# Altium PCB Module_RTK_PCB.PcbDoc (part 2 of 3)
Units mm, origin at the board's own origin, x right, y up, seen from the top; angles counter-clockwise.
Board outline 99.98 x 60 mm, 4 copper layers (Top Layer, gnd, vcc, Bottom Layer), stack 1.536 mm thick; 168 components, 121 nets, 582 pads, 666 vias.
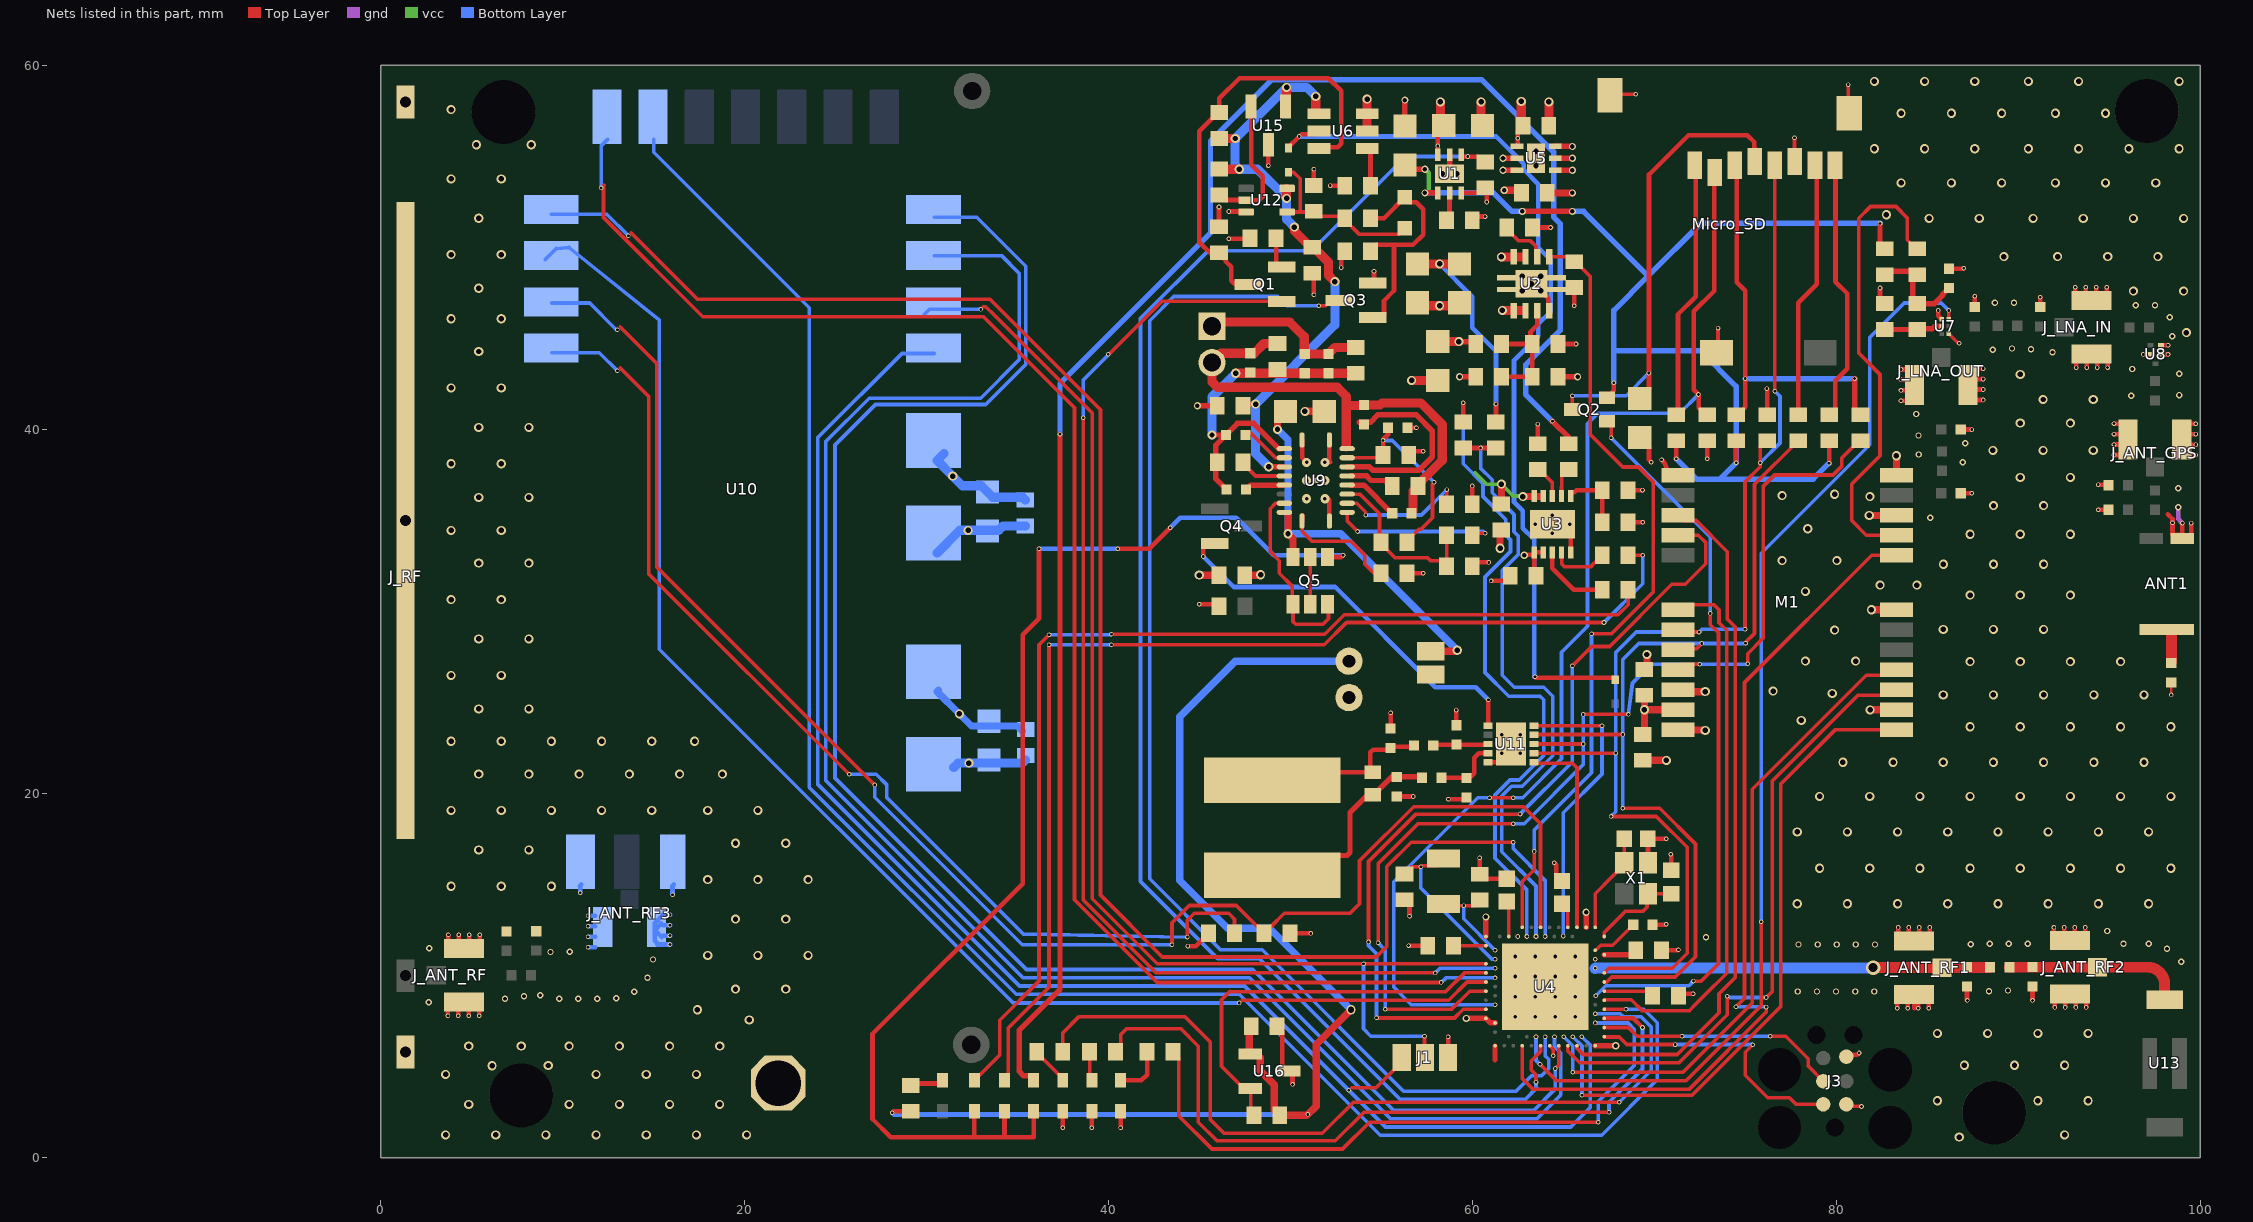
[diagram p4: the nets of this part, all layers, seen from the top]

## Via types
v1: diameter 0.5, hole 0.3, Top Layer to Bottom Layer, 281 vias
v2: diameter 0.25, hole 0.15, Top Layer to Bottom Layer, 274 vias
v3: diameter 0.35, hole 0.2, Top Layer to Bottom Layer, 58 vias
v4: diameter 0.5, hole 0.2, Top Layer to Bottom Layer, 30 vias
v5: diameter 0.4, hole 0.25, Top Layer to Bottom Layer, 20 vias
v6: diameter 0.8, hole 0.5, Top Layer to Bottom Layer, 2 vias
v7: diameter 0.5, hole 0.35, Top Layer to Bottom Layer, 1 vias

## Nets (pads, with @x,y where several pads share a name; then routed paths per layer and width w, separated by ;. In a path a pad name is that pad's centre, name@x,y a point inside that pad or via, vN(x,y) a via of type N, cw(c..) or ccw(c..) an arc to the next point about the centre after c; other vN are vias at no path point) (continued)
GND: ANT1.1 C1.1 C2.1 C3.1 C4.1 C5.1 C6.1 C7.1 C8.1 C9.1 C10.1 C11.1 C12.1 C13.1 C14.1 C15.1 C16.1 C17.2 C18.1 C19.2 C20.2 C22.1 C23.1 C24.1 C25.1 C26.1 C27.2 C28.1 C29.1 C30.1 C31.1 C32.1 C33.1 C35.1 C36.1 C37.1 C38.1 C39.1 C40.1 C41.1 C42.2 C43.1 C44.2 C45.1 C46.1 C47.1 C48.1 C49.2 C51.2 C53.2 C54.1 C55.1 C56.2 C60.1 C62.1 J1.1 J3.5 J_ANT_GPS.2 J_ANT_RF1.2 J_ANT_RF2.2 J_ANT_RF3.2 J_ANT_RF.2 J_BAT.1 J_charge_5v.1 J_LNA_IN.2 J_LNA_OUT.2 J_RF.2 J_RF.3 LED4.2 LED5.2 LED6.2 M1.2 M1.7 M1.10 M1.12 M1.13 M1.24 Micro_SD.0 Micro_SD.6 PAD_GND.0 Q3.2 R3.1 R7.1 R8.1 R9.1 R16.1 R20.1 R24.1 R25.2 R30.1 R33.2 R36.1 R38.1 R42.1 R48.2 R49.2 R51.1 U1.0 U1.3 U1.5 U2.0 U2.4 U3.0 U3.5 U4.74 U4.AD2 U4.B7 U4.F23 U5.0 U5.2 U5.3 U5.5 U7.1 U7.4 U8.2 U8.3 U8.5 U9.1 U9.11 U9.20 U9.21 U10.2 U10.3 U10.20 U10.22 U11.5 U11.11 U12.3 U15.3 U16.3 X1.2 | length 174
  Top Layer w0.15: v2(98.375,25.423) C40.1@98.375,26.108
  Top Layer w0.2: U11.11@62.1,22.64 U11.11@62.642,23.183 ; Micro_SD.0@67.54,58.375 67.59,58.425 v2(68.95,58.425) ; Micro_SD.0@73.39,44.225 73.475,44.31 v2(73.475,45.575) ; v2(77.675,56.025) 77.675,54.75 Micro_SD.6@77.7,54.725 ; v2(80.625,58.95) 80.625,57.44 Micro_SD.0@80.69,57.375 ; U7.4@86.154,45.267 86.678,44.743 86.715,44.743 v2(86.725,44.733)
  Top Layer w0.254: v2(3.7,7.8) J_ANT_RF.2@3.7,8.19 ; J_ANT_RF.2@3.728,11.86 v2(3.728,12.25) ; v2(4.275,7.8) J_ANT_RF.2@4.275,8.19 ; J_ANT_RF.2@4.303,11.86 v2(4.303,12.25) ; v2(4.85,7.8) J_ANT_RF.2@4.85,8.19 ; J_ANT_RF.2@4.877,11.86 v2(4.877,12.25) ; v2(5.425,7.8) J_ANT_RF.2@5.425,8.19 ; J_ANT_RF.2@5.453,11.86 v2(5.453,12.25) ; v2(37.475,1.65) LED6.2@37.475,2.55 ; v2(39.075,1.65) LED5.2@39.075,2.55 ; v2(40.654,1.65) LED4.2@40.654,2.55 ; v2(44.975,30.4) 45.964,30.4 R36.1@46.064,30.3 ; v2(46.059,52.226) 46.059,51.139 C45.1@46.061,51.137 ; v2(46.602,50.477) 47.541,50.477 47.664,50.6 R49.2@47.764,50.5 ; v2(46.602,51.978) 47.478,51.978 47.5,52 U12.3@47.55,51.95 ; v2(48.775,54.5) U15.3@48.775,55.65 ; C47.1@49.251,7.209 49.53,6.929 49.53,4.923 49.703,4.75 U16.3@49.875,4.75 50,4.75 50.1,4.65 v2(50.1,4.025) ; R30.1@49.962,12.319 v2(51.101,12.319) ; U9.1@50.625,39.425 50.625,38.45 v4@50.775,38.3 ; C37.1@51.175,48.589 51.275,48.589 v2(51.275,47.4) ; R25.2@51.275,53.411 v2(51.275,54.3) ; C55.1@51.742,41.1 C55.1@51.842,41 ; v4@52.075,36.2 52.125,36.15 U9.11@52.125,34.975 ; U9.20@52.125,39.425 52.125,38.25 52.175,38.2 ; v2(52.175,53.4) R24.1@52.964,53.4 ; v2(52.775,48.9) 52.775,49.611 C48.1@52.964,49.8 ; Q3.2@54.5,48.05 54.575,48.125 v2(54.575,48.7) ; C32.1@55.487,23.571 v2(55.487,24.437) ; C35.1@55.812,19.828 55.825,19.828 55.838,19.842 v2(56.726,19.842) ; C20.2@56.25,14.164 56.528,13.886 v2(56.528,13.264) ; R38.1@56.386,32.1 v2(57.275,32.1) ; v2(56.475,11.65) C26.1@57.528,11.65 ; C60.1@56.486,38.6 56.686,38.8 v2(57.286,38.8) ; C62.1@56.508,40.1 v2(56.908,40.1) ; U1.0@58.275,54.1 58.283,54.1 U1.0@58.725,54.542 ; J1.1@58.645,5.5 v2(58.645,6.65) ; v2(58.663,19.692) 59.55,19.692 C36.1@59.65,19.792 ; C33.1@59.1,23.758 v2(59.1,24.592) ; C56.2@59.209,46.9 C56.2@59.275,46.966 ; U1.3@59.375,53 60.475,53 R20.1@60.675,53.2 ; R42.1@59.975,32.5 60.175,32.7 v2(60.875,32.7) ; R33.2@59.975,35.9 v2(59.975,36.9) ; C3.1@59.975,51.5 60.175,51.7 v2(60.675,51.7) ; v2(60.375,16.475) C19.2@60.375,15.572 60.622,15.325 C29.1@61.875,15.325 ; R20.1@60.675,53.278 60.775,53.178 v2(60.775,52.5) ; U11.5@60.83,21.725 61.412,21.725 62.1,22.413 62.1,22.64 U11.11@62.1,22.725 ; v2(61.008,31.686) 61.772,31.686 C5.1@62.058,31.971 ; 61.225,5.35 U4.AD2@61.225,6.15 ; C54.1@62.475,53.2 62.525,53.15 C54.1@62.675,53 ; R7.1@63.575,39.222 v2(63.575,40.3) ; U2.0@63.825,47.612 63.825,47.537 64.152,47.21 64.152,46.585 U2.4@64.2,46.537 ; C53.2@64.275,56.6 C53.2@64.454,56.421 ; U5.3@64.454,55.573 64.477,55.55 U5.3@64.525,55.55 U5.3@64.548,55.573 ; v2(64.475,16.2) 64.577,16.098 64.577,15.523 C28.1@64.9,15.2 ; U5.2@64.525,54.9 U5.2@64.549,54.924 ; R3.1@64.686,44.7 v2(65.675,44.7) ; U3.5@65.375,33.25 U3.0@65.375,34.7 ; v2(65.575,46.8) R16.1@65.575,47.789 ; R9.1@68.536,34.9 v2(69.336,34.9) ; R8.1@68.536,36.675 v2(69.325,36.675) ; C43.1@69.175,39.566 69.683,39.058 69.683,38.333 v2(69.81,38.206) ; C15.1@69.35,26.853 69.403,26.8 C15.1@69.425,26.822 C15.1@69.567,26.964 ; X1.2@69.725,16.35 69.625,16.45 C18.1@69.625,17.525 v2(70.625,17.525) ; C27.2@69.883,12.8 70.6,12.8 v2(70.625,12.825) ; C31.1@70.375,11.4 71.275,11.4 v2(71.3,11.425) ; v2(70.375,38.333) 70.557,38.152 70.678,37.773 70.951,37.5 M1.13@71.275,37.5 ; v2(70.875,16.675) 70.9,16.65 C17.2@70.9,15.8 ; C30.1@71.3,8.9 71.325,8.875 71.45,9 v2(72.103,9) ; v2(72.875,38.4) R48.2@72.875,39.389 ; v2(76.15,42.25) 76.175,42.225 R51.1@76.175,40.811 ; J3.5@80.525,5.55 80.628,5.653 81.127,5.653 v2(81.224,5.749) ; C44.2@82.375,47.111 v2(82.375,47.775) ; M1.10@83.275,35.3 M1.10@83.35,35.225 ; v2(83.319,8.202) J_ANT_RF1.2@83.319,8.592 ; J_ANT_RF1.2@83.375,12.26 v2(83.375,12.65) ; v2(83.525,41.575) J_LNA_OUT.2@83.915,41.575 ; v2(83.525,42.15) J_LNA_OUT.2@83.915,42.15 ; v2(83.525,42.725) J_LNA_OUT.2@83.915,42.725 ; v2(83.525,43.3) J_LNA_OUT.2@83.915,43.3 ; v2(83.894,8.202) J_ANT_RF1.2@83.894,8.592 ; J_ANT_RF1.2@83.95,12.26 v2(83.95,12.65) ; 84.249,8.202 J_ANT_RF1.2@84.249,8.592 ; v2(84.469,8.202) J_ANT_RF1.2@84.469,8.592 ; J_ANT_RF1.2@84.525,12.26 v2(84.525,12.65) ; v2(85.043,8.202) J_ANT_RF1.2@85.043,8.592 ; J_ANT_RF1.2@85.1,12.26 v2(85.1,12.65) ; v2(85.567,46.542) 85.567,46.254 U7.1@85.754,46.067 ; C42.2@86.154,48.833 86.954,48.833 v2(86.979,48.858) ; C22.1@86.808,36.5 v2(87.412,36.5) ; C23.1@86.808,40 v2(87.412,40) ; C41.1@87.15,9.405 87.15,8.663 v2(87.175,8.638) ; C24.1@87.575,46.733 v2(87.575,47.324) ; J_LNA_OUT.2@87.66,41.625 v2(88.05,41.625) ; J_LNA_OUT.2@87.66,42.2 v2(88.05,42.2) ; J_LNA_OUT.2@87.66,42.775 v2(88.05,42.775) ; J_LNA_OUT.2@87.66,43.35 v2(88.05,43.35) ; v2(90.75,8.638) C46.1@90.75,9.405 ; C25.1@91.175,46.733 v2(91.175,47.269) ; J_ANT_RF2.2@91.926,12.258 v2(91.926,12.648) ; v2(91.974,8.252) J_ANT_RF2.2@91.974,8.642 ; J_ANT_RF2.2@92.501,12.258 v2(92.501,12.648) ; v2(92.55,8.252) J_ANT_RF2.2@92.55,8.642 ; J_ANT_RF2.2@93.075,12.258 v2(93.075,12.648) ; J_LNA_IN.2@93.101,47.433 v2(93.101,47.823) ; v2(93.124,8.252) J_ANT_RF2.2@93.124,8.642 ; v2(93.149,43.402) J_LNA_IN.2@93.149,43.792 ; J_ANT_RF2.2@93.651,12.258 v2(93.651,12.648) ; J_LNA_IN.2@93.676,47.433 v2(93.676,47.823) ; v2(93.699,8.252) J_ANT_RF2.2@93.699,8.642 ; v2(93.725,43.402) J_LNA_IN.2@93.725,43.792 ; J_LNA_IN.2@94.25,47.433 v2(94.25,47.823) ; v2(94.299,43.402) J_LNA_IN.2@94.299,43.792 ; v2(94.364,35.592) C39.1@94.896,35.592 ; v2(94.364,36.975) 94.896,36.975 C38.1@94.933,36.938 ; J_LNA_IN.2@94.826,47.433 v2(94.826,47.823) ; v2(94.874,43.402) J_LNA_IN.2@94.874,43.792 ; v2(95.227,38.601) J_ANT_GPS.2@95.617,38.601 ; v2(95.227,39.176) J_ANT_GPS.2@95.617,39.176 ; v2(95.227,39.75) J_ANT_GPS.2@95.617,39.75 ; v2(95.227,40.326) J_ANT_GPS.2@95.617,40.326 ; v2(96.827,44.125) U8.5@97.227,44.125 ; U8.2@97.802,44.125 v2(98.196,44.125) ; U8.3@97.802,44.625 v2(98.196,44.625) ; 98.171,35.353 98.44,35.084 v2(98.44,34.875) 98.44,34.217 98.448,34.225 ANT1.1@98.985,34.225 ; v2(98.985,34.861) ANT1.1@98.985,34.225 ; ANT1.1@99.012,34.037 98.985,34.064 ANT1.1@98.985,34.225 ; J_ANT_GPS.2@99.333,38.599 v2(99.723,38.599) ; J_ANT_GPS.2@99.333,39.175 v2(99.723,39.175) ; J_ANT_GPS.2@99.333,39.749 v2(99.723,39.749) ; J_ANT_GPS.2@99.333,40.324 v2(99.723,40.324) ; v2(99.466,34.861) 99.466,34.286 ANT1.1@99.475,34.277
  Top Layer w0.3: v5(44.875,41.3) C51.2@45.964,41.3 ; C2.1@56.275,56.667 v5(56.275,58.1) ; U1.0@58.725,54.542 U1.5@58.725,55.1 ; v5(61.662,54.9) U5.5@62.425,54.9 ; C7.1@63.286,51.1 v2(64.275,51.1) ; U5.3@64.571,55.55 v5(65.475,55.55) ; U5.2@64.573,54.9 v5(65.475,54.9)
  Top Layer w0.4: v1(44.975,32) C49.2@46.053,32 ; v1(50.775,41) 51.51,41 51.576,40.934 C55.1@51.742,41.1 ; v1(61.5,33.478) C8.1@61.5,34.449 ; v5(61.725,53.15) 62.525,53.15 C54.1@62.594,53.15 ; C16.1@69.235,21.826 v1(70.635,21.826) ; C15.1@69.567,26.964 v1(69.567,27.642) ; M1.24@71.575,23.5 72.75,23.5 v1(72.775,23.475) ; v1(81.783,35.282) 83.268,35.282 M1.10@83.3,35.25 ; v1(81.825,24.6) M1.2@83.225,24.6 ; v1(81.9,30.1) M1.7@83.275,30.1 M1.7@83.3,30.1 ; M1.12@83.275,37.5 v1(83.275,38.561)
  Top Layer w0.5: v1(56.64,42.7) C6.1@58.075,42.7 ; C4.1@57.375,46.8 v1(58.175,46.8) C56.2@59.275,46.8 ; C1.1@60.458,57.211 v1(60.458,58) ; C53.2@64.183,57.011 v1(64.183,58)
  gnd w0.254: v3(98.749,35.723) 98.749,35.098 v2(98.985,34.861)
  gnd w0.5: 64.398,7.261 64.525,7.388 v4(64.525,7.75) ; v4(62.325,8.85) v4(62.325,9.95) ; v4(62.325,8.85) v4(62.325,7.75) v4(63.425,7.75) ; v4(62.325,8.85) v4(63.425,8.85) ; v4(62.325,9.95) v4(62.325,11.05) v4(63.425,11.05) ; v4(62.325,9.95) v4(63.425,9.95) ; v4(63.425,7.75) v4(63.425,8.85) ; v4(63.425,7.75) v4(64.525,7.75) ; v4(63.425,8.85) v4(63.425,9.95) ; v4(63.425,8.85) v4(64.525,8.85) ; v4(63.425,9.95) v4(63.425,11.05) ; v4(63.425,9.95) v4(64.525,9.95) ; v4(63.425,11.05) v4(64.525,11.05) ; v4(64.525,7.75) v4(64.525,8.85) ; v4(64.525,7.75) v4(65.625,7.75) v4(65.625,8.85) ; v4(64.525,8.85) v4(64.525,9.95) ; v4(64.525,8.85) v4(65.625,8.85) ; v4(64.525,9.95) v4(64.525,11.05) ; v4(64.525,9.95) v4(65.625,9.95) ; v4(64.525,11.05) v4(65.625,11.05) v4(65.625,9.95) ; v4(65.625,8.85) v4(65.625,9.95)
  Bottom Layer w0.254: v2(10.966,14.55) 10.966,14.895 10.941,14.92 U10.20@11.026,15.005 ; v2(11.4,11.562) J_ANT_RF3.2@11.79,11.562 ; v2(11.4,12.137) J_ANT_RF3.2@11.79,12.137 ; v2(11.4,12.712) J_ANT_RF3.2@11.79,12.712 ; v2(11.4,13.287) J_ANT_RF3.2@11.79,13.287 ; J_ANT_RF3.2@15.425,12.862 J_ANT_RF3.2@15.063,12.5 ; J_ANT_RF3.2@15.44,12.123 J_ANT_RF3.2@15.063,12.5 ; J_ANT_RF3.2@15.461,13.287 15.063,12.889 J_ANT_RF3.2@15.063,12.5 ; J_ANT_RF3.2@15.508,12.201 v2(15.898,12.201) ; J_ANT_RF3.2@15.508,12.775 v2(15.898,12.775) ; J_ANT_RF3.2@15.508,13.351 v2(15.898,13.351) ; v2(15.898,11.71) 15.898,11.712 15.212,11.712 15.244,11.744 15.063,11.925 J_ANT_RF3.2@15.063,12.5 ; v2(16.041,14.45) 16.041,14.94 U10.22@16.106,15.005
  Bottom Layer w0.4: U10.2@30.65,25.675 30.575,25.6 v1(31.8,24.375) 32.466,23.709 33.425,23.709 34.978,23.709 C12.1@35.267,23.419
  Bottom Layer w0.5: U10.3@30.575,33.22 U10.3@31.825,34.47 ; v1(32.273,34.459) v1@32.284,34.449 ; C10.1@35.425,34.703 34.192,34.703 33.96,34.47 33.35,34.47 v1@32.273,34.47 ; U10.3@31.825,34.47 v1@32.273,34.47 ; U10.3@31.825,34.47 v1@32.273,34.47
  other v1: 86.725,1.125 3.57,1.252 6.327,1.252 9.085,1.252 11.842,1.252 14.599,1.252 17.35,1.252 20.107,1.252 92.518,1.252 4.847,2.925 10.362,2.925 13.119,2.925 15.876,2.925 18.627,2.925 85.529,3.127 91.043,3.127 93.8,3.127 3.57,4.575 11.842,4.575 14.599,4.575 17.35,4.575 6.131,5.05 9.212,5.064 87.004,5.077 89.761,5.077 92.518,5.077 4.847,6.125 7.731,6.125 10.356,6.125 13.119,6.125 15.876,6.125 18.633,6.125 85.529,6.825 88.286,6.825 91.043,6.825 93.8,6.825 20.257,7.565 17.401,8.125 19.5,9.264 22.257,9.264 17.975,11.109 20.732,11.109 23.489,11.109 19.5,13.109 22.257,13.109 77.825,13.95 80.582,13.95 83.339,13.95 86.096,13.95 88.854,13.95 91.611,13.95 94.368,13.95 97.125,13.95 3.871,14.909 6.629,14.909 9.386,14.909 17.975,15.275 20.732,15.275 23.489,15.275 79.05,15.9 81.807,15.9 84.564,15.9 87.321,15.9 90.079,15.9 92.836,15.9 95.593,15.9 98.35,15.9 5.396,16.909 8.154,16.909 19.5,17.275 22.257,17.275 77.825,17.9 80.582,17.9 83.339,17.9 86.096,17.9 88.854,17.9 91.611,17.9 94.368,17.9 97.125,17.9 3.871,19.075 6.629,19.075 9.386,19.075 12.143,19.075 14.9,19.075 17.975,19.075 20.732,19.075 79.05,19.85 81.807,19.85 84.564,19.85 87.321,19.85 90.079,19.85 92.836,19.85 95.593,19.85 98.35,19.85 5.396,21.075 8.154,21.075 10.911,21.075 13.668,21.075 16.425,21.075 18.775,21.075 80.332,21.725 83.089,21.725 85.846,21.725 88.604,21.725 91.361,21.725 94.118,21.725 96.875,21.725 3.871,22.875 6.629,22.875 9.386,22.875 12.143,22.875 14.9,22.875 17.25,22.875 87.321,23.675 90.079,23.675 92.836,23.675 95.593,23.675 98.35,23.675 78.048,24.027 5.396,24.65 8.154,24.65 85.846,25.423 88.604,25.423 91.361,25.423 94.118,25.423 96.875,25.423 79.749,25.502 76.503,25.629 3.871,26.495 6.629,26.495 87.321,27.25 90.079,27.25 92.836,27.25 95.593,27.25 78.274,27.277 81.031,27.277 5.396,28.495 8.154,28.495 79.876,28.977 85.846,29.025 88.604,29.025 91.361,29.025 3.871,30.661 6.629,30.661 87.321,30.9 90.079,30.9 92.836,30.9 78.274,31.106 82.375,31.45 84.4,31.45 85.85,32.6 88.607,32.6 91.364,32.6 5.396,32.661 8.154,32.661 76.992,32.802 80.003,32.802 87.321,34.25 90.079,34.25 92.836,34.25 3.871,34.461 6.629,34.461 78.401,34.55 88.607,35.825 91.364,35.825 5.396,36.275 8.154,36.275 81.814,36.32 76.996,36.373 79.88,36.447 90.079,37.375 92.836,37.375 3.871,38.12 6.629,38.12 88.575,38.85 91.332,38.85 94.089,38.85 5.396,40.12 8.154,40.12 90.079,40.35 92.836,40.35 91.332,41.65 94.089,41.65 3.871,42.286 6.629,42.286 90.079,43.025 5.396,44.286 99.2,45.321 3.871,46.086 6.629,46.086 96.293,47.6 99.05,47.6 5.396,47.76 89.175,49.502 92.129,49.502 94.886,49.502 97.643,49.502 3.871,49.605 6.629,49.605 5.396,51.605 85.068,51.602 87.825,51.602 90.779,51.602 93.536,51.602 96.293,51.602 99.05,51.602 82.725,51.8 83.536,53.552 86.293,53.552 89.05,53.552 92.004,53.552 94.761,53.552 97.518,53.552 3.871,53.771 6.629,53.771 82.061,55.427 84.818,55.427 87.575,55.427 90.529,55.427 93.286,55.427 96.043,55.427 98.8,55.427 5.269,55.644 8.281,55.644 83.536,57.377 86.293,57.377 89.05,57.377 92.004,57.377 94.761,57.377 3.871,57.571 82.061,59.125 84.818,59.125 87.575,59.125 90.529,59.125 93.286,59.125 98.8,59.125
  other v2: 66.725,10.9 62.475,12.15
  other v3: 2.655,8.542 6.839,8.736 9.808,8.736 10.858,8.736 11.908,8.736 12.958,8.758 7.882,8.861 8.775,8.922 13.946,9.114 77.858,9.13 78.908,9.13 79.958,9.13 81.008,9.13 82.058,9.13 88.357,9.149 89.407,9.184 14.664,9.88 98.918,10.768 14.969,10.884 9.338,11.302 10.388,11.314 98.141,11.475 2.678,11.508 77.898,11.708 78.948,11.708 79.998,11.708 81.048,11.708 82.098,11.708 87.348,11.727 88.398,11.747 89.448,11.748 90.498,11.752 95.748,11.752 97.128,11.75 72.816,12.112 94.85,12.45 85.125,35.15 98.764,36.773 86.915,38.211 84.503,38.626 87.064,39.25 84.485,39.676 84.359,40.853 96.172,41.863 98.817,41.894 98.804,43.064 96.225,43.323 91.846,44.25 88.573,44.377 90.67,44.411 89.62,44.449 98.431,45.13 98.294,46.171 96.431,46.832 97.481,46.837 88.686,46.956 89.736,46.972
  other v4: 61.6,22.225 62.6,22.225 61.6,23.225 62.6,23.225 64.375,34.3 63.425,34.8 65.325,34.8 64.375,35.3 50.875,36.2 51.875,36.2 50.875,37.2 51.875,37.2 50.875,38.2 51.875,38.2
GPS_EXTINT: M1.4 U4.AC17 | length 36
  Top Layer w0.2: v2(65.5,4.7) 71.547,4.7 75.35,8.503 75.35,20.234 81.616,26.5 82.975,26.5 M1.4@83.275,26.8
  Bottom Layer w0.2: v2(65,6.65) 65.5,6.15 v2(65.5,4.7)
GPS_GEOFENCE_STAT: M1.16 U4.U1 | length 46.2
  Top Layer w0.2: v2(54.275,11.85) 54.275,16.271 56.879,18.875 v2(62.6,18.875) ; v2(54.715,7.681) 54.726,7.671 58.994,7.671 59.473,8.15 U4.U1@60.725,8.15 ; v2(65.475,27.025) 66.531,28.081 67.519,28.081 70.938,31.5 71.672,31.5 72.8,32.628 72.8,33.792 72.392,34.2 M1.16@71.275,34.2
  Bottom Layer w0.2: v2(54.275,11.85) 54.275,11.648 54.715,11.207 v2(54.715,7.681) ; v2(62.6,18.875) 65.475,21.75 v2(65.475,27.025)
GPS_LNA_EN: U4.AC11 U7.6 | length 60.8
  Top Layer w0.2: v2(63.693,5.125) 64.597,4.221 71.71,4.221 75.85,8.361 v2(75.85,12.961) ; U7.6@86.154,46.067 v2(86.154,46.542)
  Bottom Layer w0.2: v2(63.475,6.65) 63.475,5.343 v2(63.693,5.125) ; v2(75.85,12.961) 75.85,33.207 81.804,39.161 81.804,45.054 83.704,46.954 85.742,46.954 v2(86.154,46.542)
GPS_nRST: M1.8 U4.AD8 | length 48.4
  Top Layer w0.2: U4.AD8@62.725,6.15 62.725,4.35 63.325,3.75 71.881,3.75 76.115,7.984 76.115,8.265 v2(76.125,8.275) ; v2(74.461,8.291) 74.925,8.755 74.925,26.1 81.925,33.1 M1.8@83.275,33.1
  Bottom Layer w0.2: v2(74.461,8.291) 74.469,8.283 76.117,8.283 v2(76.125,8.275)
GPS_nSAFEBOOT: M1.1 U4.AC19 | length 36.2
  Top Layer w0.2: U4.AC19@65.475,6.65 v2(65.5,6.65) ; v2(66,3.425) 72.05,3.425 76.925,8.3 76.925,20.525 79.9,23.5 M1.1@83.275,23.5
  Bottom Layer w0.2: v2(65.5,6.65) 66,6.15 v2(66,3.425)
GPS_RTK_STAT: M1.15 U4.AD20 | length 38.5
  Top Layer w0.2: U4.AD20@65.725,6.15 65.725,6.008 66.062,5.671 71.241,5.671 73.529,7.959 73.529,9 74.425,9.896 74.425,29.15 73.985,29.59 73.985,33.29 72.276,35 71.575,35 M1.15@71.275,35.3
GPS_TIMEPULSE: M1.3 U4.AD18 | length 34.5
  Top Layer w0.2: U4.AD18@65.225,6.15 65.225,5.866 65.874,5.217 71.335,5.217 73.975,7.857 73.975,8.875 v2(73.983,8.875) ; v2(76.125,8.8) 76.45,9.125 76.45,20.692 81.158,25.4 82.975,25.4 M1.3@83.275,25.7
  Bottom Layer w0.2: v2(73.983,8.875) 74.058,8.8 v2(76.125,8.8)
IRQ_NFC: U4.B17 U11.10 | length 16.2
  Top Layer w0.2: U11.10@63.37,23.725 v2(67.1,23.725) ; U4.B17@64.975,12.15 v2(64.975,12.175)
  Bottom Layer w0.2: v2(64.975,12.175) 64.975,18.95 67.1,21.075 v2(67.1,23.725)
LED4: R19.2 U4.Y23 | length 36.3
  Top Layer w0.2: R19.2@43.533,5.825 43.839,5.519 43.839,2.311 45.675,0.475 52.85,0.475 54.325,1.95 v2(66.9,1.95)
  Bottom Layer w0.2: v2(66.725,7.4) 68.525,7.4 68.875,7.05 68.875,5.058 66.9,3.083 v2(66.9,1.95)
LED5: R27.2 U4.W24 | length 41.4
  Top Layer w0.2: R27.2@40.375,5.825 40.654,6.104 40.654,6.754 40.975,7.075 43.975,7.075 44.925,6.125 44.925,1.95 45.95,0.925 52.45,0.925 54.025,2.5 v2(67.488,2.5)
  Top Layer w0.254: U4.W24@67.225,7.65 68.825,7.65 v2(69.325,7.15)
  Bottom Layer w0.2: v2(67.488,2.5) 67.488,3.038 69.325,4.875 v2(69.325,7.15)
LED6(H_B): R28.2 U4.V23 | length 46.1
  Top Layer w0.2: R28.2@37.475,5.825 37.475,6.85 38.375,7.75 44.175,7.75 45.575,6.35 45.575,2.1 46.336,1.339 51.739,1.339 53.45,3.05 v2(68.05,3.05)
  Bottom Layer w0.2: v2(66.725,7.9) 68.1,7.9 68.25,7.75 69.225,7.75 69.8,7.175 69.8,4.8 v2(68.05,3.05)
MES_VBAT: R21.1 R22.2 U4.B11 | length 34.2
  Top Layer w0.254: R22.2@59.575,39 59.586,38.989 v2(60.431,38.989) R21.1@61.275,38.989
  Bottom Layer w0.2: v2(60.431,38.989) 60.431,37.878 61.069,37.24 61.069,36.528 62.269,35.328 62.269,34.383 62.508,34.144 62.508,33.144 61.625,32.261 61.625,26.5 62.275,25.85 63.9,25.85 64.4,25.35 64.4,22.075 62.725,20.4 62.133,20.4 61.6,19.867 61.6,16.8 63.475,14.925 v2(63.475,12.15)
MES_VBAT_nEN: R22.1 U4.B9 | length 36.5
  Top Layer w0.254: R22.1@59.475,40.411 v2(59.475,41.467)
  Bottom Layer w0.2: v2(59.475,41.467) 59.475,38.116 60.561,37.03 60.561,36.318 61.815,35.064 61.815,34.195 62.075,33.935 62.075,33.3 60.675,31.9 60.675,26.65 61.975,25.35 63.7,25.35 63.9,25.15 63.9,22.096 62.554,20.75 62.05,20.75 61.225,19.925 61.225,16.457 62.975,14.707 v2(62.975,12.15)
nCS_NFC: U4.A20 U11.6 | length 11.3
  Top Layer w0.2: U11.6@63.37,21.725 63.42,21.675 65.475,21.675 65.725,21.425 U4.A20@65.725,12.65
NetANT1_3: ANT1.3 C40.2 | length 1.8
  Top Layer w0.15: C40.2@98.35,27.2 ccw(c98.375,27.2) C40.2@98.375,27.175
  Top Layer w0.6: C40.2@98.375,27.225 ANT1.3@98.375,29.025
NetANT2_1: ANT2.1 C34.1 C35.2 L6.1 | length 11.4
  Top Layer w0.3: ANT2.1@48.975,15.525 50.049,16.599 53.081,16.599 53.256,16.775 53.256,18.956 C34.1@54.174,19.874 ; C34.1@54.52,19.905 55.541,20.926 57.158,20.926 L6.1@57.208,20.875
NetANT2_2: ANT2.2 C32.2 C34.2 L2.1 | length 9.2
  Top Layer w0.254: ANT2.2@48.975,20.725 49.425,21.175 54.2,21.175 54.376,21.351 54.376,22.263 54.525,22.412 C32.2@55.334,22.412 ; C32.2@55.334,22.361 C32.2@55.334,22.412 ; L2.1@56.767,22.64 56.699,22.572 55.555,22.572 C32.2@55.487,22.504 55.343,22.361 55.343,22.403 C32.2@55.334,22.412
NetC3_2: C3.2 U1.2 | length 1.4
  Top Layer w0.254: C3.2@58.675,51.6 58.725,51.65 U1.2@58.725,53
NetC7_2: C7.2 U2.6 | length 2.5
  Top Layer w0.2: C7.2@61.864,50.811 62.076,50.811 62.524,50.363 63.178,50.363 63.475,50.066 63.475,49.562 U2.6@63.55,49.487
NetC17_1: C17.1 U4.B24 X1.1 | length 5
  Top Layer w0.2: U4.B24@67.225,12.15 67.225,12.371 68.4,13.546 69.371,13.546 69.575,13.75 69.575,14.375 X1.1@69.625,14.425 ; X1.1@69.8,14.425 69.875,14.5 C17.1@70.9,14.5
NetC18_2: C18.2 U4.A23 X1.3 | length 5.4
  Top Layer w0.2: U4.A23@66.725,12.7 66.725,14.501 67.678,15.454 68.325,16.1 X1.3@68.325,16.2 ; X1.3@68.237,16.288 68.325,16.375 C18.2@68.325,17.525
NetC19_1: C19.1 U4.D2 Y2.1 | length 5.3
  Top Layer w0.2: Y2.1@58.4,13.975 58.531,13.844 59.5,13.844 60.069,13.844 C19.1@60.375,14.15
  Bottom Layer w0.2: v2(59.5,13.849) 59.5,13.125 v2(61.225,11.4)
NetC20_1: C20.1 U4.F2 Y2.2 | length 9.6
  Top Layer w0.2: C20.1@56.025,15.586 C20.1@56.25,15.586 56.639,15.975 v2(57.151,15.975) 57.165,15.975 57.22,16.03 58,16.03 Y2.2@58.4,16.43
  Bottom Layer w0.2: v2(57.151,15.975) 57.151,14.796 61.038,10.91 61.215,10.91 v2(61.225,10.9)
NetC21_1: C21.1 R1.1 R3.2 R53.1 U2.3 | length 6.8
  Top Layer w0.254: R1.1@61.586,42.9 C21.1@63.175,42.9 ; R53.1@61.586,44.7 R3.2@63.075,44.7 ; R3.2@63.175,44.6 63.175,45.369 63.55,45.744 U2.3@63.55,46.325 ; C21.1@63.264,42.9 R3.2@63.264,44.7
NetC26_2: C26.2 U4.C1 | length 1.8
  Top Layer w0.2: C26.2@58.95,11.65 U4.C1@60.725,11.65
NetC27_1: C27.1 U4.D23 | length 2.7
  Top Layer w0.2: U4.D23@66.725,11.4 66.75,11.4 67.025,11.675 67.692,11.675 C27.1@68.817,12.8
NetC28_2: C28.2 U4.A18 | length 1.3
  Top Layer w0.2: U4.A18@65.225,12.675 C28.2@65.225,13.925
NetC29_2: C29.2 U4.B5 | length 1.9
  Top Layer w0.2: C29.2@61.875,14.075 61.975,13.975 U4.B5@61.975,12.175
NetC30_2: C30.2 U4.N24 | length 2.8
  Top Layer w0.2: U4.N24@67.225,9.15 69.628,9.15 C30.2@69.878,8.9
NetC31_2: C31.2 U4.E24 | length 1.7
  Top Layer w0.3: U4.E24@67.225,11.15 68.696,11.15 68.825,11.279 C31.2@68.825,11.375
NetC33_2: C33.2 L2.2 U11.3 | length 3
  Top Layer w0.254: L2.2@57.833,22.64 57.876,22.683 60.787,22.683 U11.3@60.83,22.725
NetC36_2: C36.2 L6.2 U11.4 | length 3.4
  Top Layer w0.254: L6.2@58.275,20.875 59.633,20.875 C36.2@59.65,20.858 ; C36.2@59.892,20.926 60.075,21.108 60.075,21.977 60.323,22.225 U11.4@60.83,22.225
NetC41_2: C41.2 J_ANT_RF1.1 L7.1 U4.H23 | length 21.7
  Top Layer w0.6: v6(81.99,10.438) L7.1@88.392,10.438
  Bottom Layer w0.6: v2(66.725,10.4) 66.744,10.419 81.971,10.419 v6(81.99,10.438)
NetC42_1: C42.1 L5.2 R29.1 R31.2 | length 5.8
  Top Layer w0.3: R29.1@82.375,48.7 84.175,48.7 84.175,47.111 84.368,46.918 L5.2@84.425,46.918 85.36,46.918 85.813,47.371 85.813,47.425 C42.1@86.154,47.767
NetC43_2: C43.2 Micro_SD.4 Q2.3 | length 25.9
  Top Layer w0.2: Q2.3@65.475,41.1 v2(65.475,41.85)
  Top Layer w0.254: C43.2@69.175,41.7 69.683,42.208 69.683,43.1 69.683,54.008 71.85,56.175 75.075,56.175 75.456,55.794 75.456,55.469 75.775,55.15 Micro_SD.4@75.775,54.8
  Bottom Layer w0.2: v2(65.475,41.85) 68.425,41.85 v2(69.675,43.1)
NetC45_2: C45.2 Q1.3 R2.1 U6.6 | length 22.8
  Top Layer w0.254: C45.2@45.675,49.6 44.975,50.3 44.975,56.387 45.999,57.411 R2.1@46.075,57.411 46.075,58.199 47.184,59.308 52.067,59.308 52.775,58.6 52.775,55.7 52.575,55.5 U6.6@51.975,55.5 ; C45.2@46.075,49.589 46.151,49.589 46.431,49.309 46.431,49.233 46.727,48.937 46.727,48.173 46.9,48 Q1.3@47.075,48
NetC46_2: C46.2 J_ANT_RF2.1 L7.2 U13.1 | length 9.9
  Top Layer w0.6: L7.2@89.483,10.463 90.75,10.463 94.15,10.463 97.071,10.463 cw(c97.071,9.524) 98.01,9.524 U13.1@98.01,8.676
NetC48_2: C48.2 D2.1 Q3.1 R23.1 | length 12.7
  Top Layer w0.254: C48.2@54.386,49.8 54.386,49.876 54.666,50.156 56.719,50.156 57.275,50.711 57.275,52.1 56.898,52.477 56.548,52.477 56.475,52.55 D2.1@56.475,52.8 ; Q3.1@54.5,46.15 54.95,46.15 55.123,46.323 55.123,47.084 55.675,47.636 55.675,50.1 ; R23.1@54.675,51.6 55.125,51.6 D2.1@56.275,52.75
NetC50_1: C50.1 C52.1 C58.1 J2.1 | length 9.1
  Top Layer w0.5: J2.1@45.675,45.9 49.946,45.9 50.746,45.101 50.746,44.188 C52.1@50.775,44.158 C50.1@52.075,44.158 52.431,44.514 C58.1@53.342,44.514
NetC50_2: C50.2 C52.2 C57.1 C58.2 C61.1 C63.2 C64.2 C68.1 U9.2 | length 17.8
  Top Layer w0.3: v1(45.675,39.7) C61.1@46.442,39.7 ; C68.1@45.875,37.8 45.875,37.3 C57.1@46.475,36.7 ; C68.1@45.875,38.5 45.888,38.513 45.888,39.146 C61.1@46.442,39.7 ; U9.2@49.475,38.944 49.351,38.944 47.961,40.333 47.075,40.333 C61.1@46.442,39.7
  Top Layer w0.5: v1(46.98,43.092) C52.2@50.775,43.092 C50.2@52.075,43.092 C58.2@53.402,43.092
  Bottom Layer w0.5: v1(45.675,39.7) 45.675,41.787 v1(46.98,43.092)
NetC57_2: C57.2 U9.6 | length 2.2
  Top Layer w0.3: C57.2@47.575,36.7 47.575,36.733 47.792,36.95 U9.6@49.65,36.95
NetC60_2: C60.2 C62.2 R26.1 U9.18 | length 11.1
  Top Layer w0.2: U9.18@53.175,38.456 53.275,38.456 53.281,38.45 54.903,38.45 C60.2@54.953,38.5 ; R26.1@56.386,33.8 56.386,33.876 57.038,34.528 57.163,34.528 57.792,35.158 57.792,37.017 v2(57.875,37.1)
  Top Layer w0.254: C60.2@55.086,38.6 55.086,39.464 55.342,39.719 C62.2@55.342,40.1
  Bottom Layer w0.2: v2(55.075,39.4) 55.575,39.4 v2(57.875,37.1)
NetC61_2: C61.2 U9.3 | length 2.7
  Top Layer w0.2: C61.2@47.575,39.7 47.663,39.788 47.829,39.788 49.16,38.456 49.644,38.456 U9.3@49.65,38.45
NetC63_1: C63.1 C64.1 C65.1 C66.1 C67.1 J2.2 U9.19 | length 26
  Top Layer w0.5: J2.2@45.675,43.9 45.675,42.621 45.971,42.325 52.555,42.325 53.05,41.83 53.05,41.322 U9.19@53.05,39.05 ; J2.2@45.875,43.9 46.167,44.192 C64.1@47.775,44.192 48,44.192 48.533,44.725 C63.1@49.05,44.725 ; 53.278,41.322 53.996,41.322 C65.1@54.025,41.351 54.903,41.351 55.018,41.467 57.133,41.467 58.325,40.275 58.325,38.304 C67.1@57.177,37.156 ; C66.1@56.666,35.5 56.718,35.552 56.718,36.621 C67.1@56.997,36.9
NetC65_2: C65.2 U9.17 | length 11
  Top Layer w0.3: U9.17@53.1,37.95 54.324,37.95 54.511,37.763 57.039,37.763 57.775,38.499 57.775,39.922 56.897,40.8 54.775,40.8 54.375,40.4 C65.2@53.775,40.4
NetC66_2: C66.2 U9.15 | length 2.9
  Top Layer w0.3: U9.15@53.275,36.944 53.281,36.95 54.025,36.95 C66.2@55.575,35.4
NetC67_2: C67.2 U9.16 | length 2.4
  Top Layer w0.3: U9.16@53.281,37.45 54.167,37.45 54.417,37.2 55.175,37.2 C67.2@55.475,36.9
NetC68_2: C68.2 U9.5 | length 2.5
  Top Layer w0.2: C68.2@47.386,38.2 47.386,38.124 48.06,37.45 49.569,37.45 U9.5@49.575,37.456
NetD1_1: D1.1 D3.1 U6.5 | length 49.6
  Top Layer w0.254: D1.1@49.875,55.5 v2(50.475,56.1) 50.602,56.227 51.377,56.227 U6.5@51.55,56.4 ; v2(63.42,26.416) 63.463,26.373 67.752,26.373 67.825,26.3 D3.1@67.825,26.26
  Bottom Layer w0.254: v2(50.475,56.1) 61.291,56.1 62.795,54.595 62.795,54.287 63.606,53.477 63.606,50.001 64.275,49.332 64.275,46.48 63.606,45.811 63.606,45.132 62.269,43.795 62.269,36.008 62.75,35.527 62.75,34.583 63.37,33.963 v2@63.37,26.42
NetD1_2: D1.2 D2.2 R23.2 R25.1 U12.4 | length 9.6
  Top Layer w0.2: U12.4@49.8,51.95 50.518,51.95 ; D1.2@49.875,54.14 50.153,54.14 50.518,53.775 50.518,51.95 ; R25.1@51.275,51.989 51.236,51.95 50.518,51.95 ; R25.1@51.375,51.9 51.566,51.709 52.854,51.709 R23.2@52.964,51.6 52.964,51.524 53.751,50.736 55.961,50.736 56.175,50.95 D2.2@56.175,51
NetLED1_2: LED1.2 R6.1 | length 96.4
  Top Layer w0.3: LED1.2@35.875,4.25 35.875,4.35 35.725,4.5 35.325,4.5 35.088,4.737 35.088,7.01 37.325,9.247 v2(37.325,39.75) ; v2(64.375,40.45) 65.275,39.55 R6.1@65.275,39.222
  Bottom Layer w0.3: v2(37.325,39.75) 37.325,42.519 45.592,50.787 45.592,55.842 48.975,59.225 60.475,59.225 64.446,55.254 64.446,51.677 64.804,51.319 64.804,45.454 62.9,43.55 62.9,41.925 v2(64.375,40.45)
NetLED2_2: LED2.2 R5.1 | length 61.3
  Top Layer w0.2: LED2.2@34.275,4.25 34.475,4.45 34.475,7.11 36.725,9.36 v2(36.725,28.171) ; v2(40.15,28.171) 51.841,28.171 53.07,29.4 v2(67.21,29.4) ; R5.1@68.536,33.1 v2(69.336,33.1)
  Bottom Layer w0.2: v2(36.725,28.171) v2(40.15,28.171) ; v2(67.21,29.4) 69.336,31.526 v2(69.336,33.1)
NetLED3_2: LED3.2 R4.1 | length 59.5
  Top Layer w0.2: LED3.2@32.625,4.25 34.021,5.646 34.021,7.546 36.175,9.7 36.175,28.171 v2(36.725,28.721) ; v2(40.15,28.75) 51.867,28.75 52.942,29.825 67.984,29.825 68.536,30.377 R4.1@68.536,31.2
  Bottom Layer w0.2: v2(36.725,28.721) 40.121,28.721 v2(40.15,28.75)
NetLED4_1: LED4.1 R19.1 | length 2.8
  Top Layer w0.254: LED4.1@40.654,4.25 41.8,4.25 42.111,4.561 R19.1@42.111,5.825
NetLED5_1: LED5.1 R27.1 | length 1.6
  Top Layer w0.2: R27.1@38.953,5.825 38.953,4.372 LED5.1@39.075,4.25
NetLED6_1: LED6.1 R28.1 | length 2.2
  Top Layer w0.2: R28.1@36.053,5.825 36.053,5.772 37.475,4.35 LED6.1@37.475,4.25
NetLED7_1: LED7.1 R37.1 | length 2.2
  Top Layer w0.254: R37.1@28.876,4.085 R37.1@29.125,3.836 ; R37.1@29.125,3.972 29.23,4.077 30.702,4.077 LED7.1@30.875,4.25
NetM1_9: M1.9 R31.1 | length 25.3
  Top Layer w0.2: M1.9@83.275,34.2 81.624,34.2 80.817,35.006 80.817,37.004 82.375,38.561 82.375,43.025 81.2,44.2 81.2,51.6 81.85,52.25 83.25,52.25 83.875,51.625 83.875,50.422 R31.1@84.175,50.122
NetMicro_SD_1: Micro_SD.1 R47.2 | length 14.9
  Top Layer w0.254: R47.2@71.175,40.811 71.099,40.811 70.842,41.068 71.275,41.068 71.275,46.325 72.25,47.3 Micro_SD.1@72.25,54.375 ; Micro_SD.1@72.225,54.3 Micro_SD.1@72.45,54.525
NetMicro_SD_3: Micro_SD.3 R40.1 R50.2 | length 22.4
  Top Layer w0.254: R40.1@74.475,40.811 74.551,40.811 74.969,41.229 v2(74.969,42.8) 74.969,47.631 74.5,48.1 Micro_SD.3@74.5,54.425 ; Micro_SD.3@74.475,54.35 Micro_SD.3@74.65,54.525
  Top Layer w0.3: v2(80.975,42.8) 80.975,41.137 R50.2@81.3,40.811
  Bottom Layer w0.3: v2(74.969,42.8) v2(80.975,42.8)
NetMicro_SD_7: Micro_SD.7 R41.2 | length 14.3
  Top Layer w0.254: R41.2@77.875,40.811 77.875,46.966 78.9,47.991 Micro_SD.7@78.9,54.375 ; Micro_SD.7@78.875,54.35 Micro_SD.7@78.9,54.375 ; Micro_SD.7@78.9,54.425 Micro_SD.7@78.9,54.375 ; Micro_SD.7@79.05,54.525 Micro_SD.7@78.9,54.375
NetMicro_SD_8: Micro_SD.8 R44.2 | length 14.6
  Top Layer w0.254: R44.2@79.575,40.811 79.651,40.811 79.908,41.068 79.908,42.671 80.575,43.339 80.575,47.475 79.925,48.125 Micro_SD.8@79.925,54.35 ; Micro_SD.8@79.9,54.275 Micro_SD.8@80.15,54.525
NetQ1_2: Q1.2 R49.1 | length 1.6
  Top Layer w0.254: Q1.2@49.2,48.95 49.2,50.425 R49.1@49.275,50.5
NetQ5_1: Q5.1 Q5.3 U9.8 | length 10.1
  Top Layer w0.2: U9.8@49.65,35.95 49.644,35.944 49.16,35.944 48.871,35.655 48.871,33.303 49.375,32.8 49.375,32.1 50.075,31.4 50.075,30.7 50.125,30.65 Q5.1@50.125,30.4 50.125,29.45 50.275,29.3 51.775,29.3 52.075,29.6 Q5.3@52.075,29.9
NetQ5_2: Q5.2 Q5.5 | length 2.5
  Top Layer w0.2: Q5.2@51.075,30.4 51.075,32.8 Q5.5@51.175,32.9
NetR4_2: R4.2 U3.3 | length 4.2
  Top Layer w0.254: U3.3@64.375,33.25 64.375,32.375 65.55,31.2 66.838,31.2 66.926,31.288 67.014,31.376 R4.2@67.014,31.2
NetR5_2: R5.2 U3.4 | length 3.2
  Top Layer w0.2: U3.4@64.875,33.25 64.892,33.233 64.892,32.617 65.056,32.454 66.468,32.454 66.731,32.717 66.807,32.717 67.114,33.024 R5.2@67.114,33.1
NetR6_2: R6.2 U3.7 | length 1.6
  Top Layer w0.2: U3.7@64.875,36.4 64.875,36.826 64.892,36.843 64.892,37.494 65.199,37.8 R6.2@65.275,37.8
NetR7_2: R7.2 U3.8 | length 1.8
  Top Layer w0.2: R7.2@63.575,37.8 63.651,37.8 64.375,37.076 U3.8@64.375,36.4
NetR8_2: R8.2 R9.2 U3.6 | length 3.8
  Top Layer w0.254: U3.6@65.375,36.35 65.375,36.525 65.398,36.548 65.573,36.548 65.7,36.675 R8.2@67.114,36.675 R9.2@67.114,34.9
NetR11_2: R11.2 U12.2 U15.2 | length 7.2
  Top Layer w0.254: R11.2@46.275,52.8 46.275,52.765 46.431,52.609 47.541,52.609 U12.2@47.55,52.6 ; U15.2@47.825,57.75 47.825,54.55 48.467,53.908 48.467,52.792 48.275,52.6 U12.2@47.975,52.6
NetR24_2: R24.2 U6.1 | length 2.1
  Top Layer w0.254: U6.1@54.275,55.5 54.386,55.389 R24.2@54.386,53.4
NetR26_2: R26.2 R39.2 R42.2 U9.14 | length 9.6
  Top Layer w0.2: U9.14@53.1,36.45 53.106,36.444 53.808,36.444 54.875,35.377 54.875,34.235 54.74,34.1 R26.2@54.975,34.1 ; R26.2@54.964,33.8 54.964,33.724 55.724,32.963 57.512,32.963 57.675,32.8 58.246,32.8 58.375,32.671 R42.2@58.375,32.4 ; R42.2@58.553,32.5 58.575,32.522 R39.2@58.575,34.1
NetR33_1: R33.1 U9.13 | length 7.3
  Top Layer w0.2: U9.13@53.1,35.95 53.625,35.95 54.125,35.45 v2(54.125,35.304) ; R33.1@58.503,35.95 R33.1@58.553,35.9 58.575,35.922 v2(58.575,36.7)
  Bottom Layer w0.2: v2(54.125,35.304) 57.179,35.304 v2(58.575,36.7)
NetR38_2: R38.2 U9.10 | length 6.1
  Top Layer w0.2: U9.10@50.625,34.975 50.631,34.969 50.631,34.403 51.18,33.854 53.321,33.854 54.075,33.1 54.075,32.6 R38.2@54.575,32.1
  Top Layer w0.254: U9.10@50.625,34.975 U9.10@50.625,35.294
NetR39_1: R39.1 U9.12 | length 9
  Top Layer w0.2: U9.12@53.1,35.45 53.1,34.975 v2(53.675,34.4) ; R39.1@60.075,34.2 60.175,34.3 v2(60.675,34.3)
  Bottom Layer w0.2: v2(53.675,34.4) 60.575,34.4 v2(60.675,34.3)
READ_INTERRUPT: R12.2 U4.J1 U16.2 | length 22.3
  Top Layer w0.2: R12.2@47.978,2.325 47.8,2.503 47.8,3.6 47.6,3.8 47.425,3.8 46.2,5.025 46.2,8.677 46.652,9.129 46.656,9.125 58.521,9.125 59.546,10.15 U4.J1@60.725,10.15
RF_BOOT0: R30.2 U4.A12 U10.18 | length 88.4
  Top Layer w0.2: 13.17,45.638 15.179,43.629 15.179,32.446 v2(27.15,20.475) ; v2(43.475,11.7) 43.475,12.9 44.425,13.85 47.008,13.85 48.157,12.701 48.233,12.701 R30.2@48.54,12.395 ; R30.2@48.54,12.319 R30.2@48.54,12.395 ; U4.A12@63.725,12.65 63.725,18.351 62.793,19.283 56.754,19.283 53.775,16.304 53.775,13.944 53.256,13.425 49.646,13.425 48.922,12.701 48.846,12.701 R30.2@48.54,12.395
  Bottom Layer w0.2: U10.18@9.416,46.95 11.491,46.95 12.953,45.488 v2(13.011,45.488) ; v2(27.15,20.475) 27.15,19.802 35.252,11.7 v2(43.475,11.7)
RF_CTS: U4.AC15 U10.7 | length 92.9
  Top Layer w0.2: U4.AC15@64.475,6.65 v2(64.491,6.65) U4.AC15@64.5,6.65
  Bottom Layer w0.2: U10.7@30.416,49.555 34.111,49.555 35.091,48.575 35.091,43.85 32.966,41.725 26.841,41.725 24.462,39.346 24.462,20.717 35.292,9.887 47.731,9.887 55.477,2.142 63.534,2.142 64.841,3.449 64.841,5.75 64.491,6.1 v2(64.491,6.65)
RF_GPIO0: U4.U24 U10.14 | length 101.2
  Top Layer w0.2: U4.U24@67.225,8.15 v2(68.425,8.15)
  Bottom Layer w0.2: U10.14@15.012,55.93 15.012,55.23 23.554,46.688 23.554,20.341 34.916,8.979 47.171,8.979 54.917,1.234 67.083,1.234 70.141,4.292 70.141,7.409 69.4,8.15 v2(68.425,8.15)
RF_GPIO1: U4.K2 U10.15 | length 86.9
  Top Layer w0.2: 12.275,53.425 12.25,53.4 12.25,51.648 17.698,46.2 33.125,46.2 38.121,41.204 38.121,14.175 42.671,9.625 v2(58.275,9.625) ; v2(61.225,9.875) U4.K2@61.225,9.9
  Bottom Layer w0.2: v2(12.116,53.275) 12.116,55.574 U10.15@12.472,55.93 ; v2(58.275,9.625) 58.525,9.875 v2(61.225,9.875)
RF_GPIO2: U4.B13 U10.16 | length 96.4
  Top Layer w0.2: 13.775,50.8 17.41,47.165 33.477,47.165 39.55,41.092 39.55,14.425 42.95,11.025 54.702,11.025 55.279,11.602 55.279,15.991 56.617,17.329 v2(62.225,17.329)
  Bottom Layer w0.2: U10.16@9.375,51.833 12.433,51.833 v2(13.616,50.65) ; v2(62.225,17.329) 62.225,16.979 63.975,15.229 v2(63.975,12.15)
RF_GPIO3: U4.L1 U10.17 | length 79.7
  Top Layer w0.2: 47.33,8.65 58.688,8.65 59.688,9.65 U4.L1@60.725,9.65
  Bottom Layer w0.2: U10.17@9.05,49.34 9.32,49.61 9.652,49.942 9.672,49.926 10.353,50 15.316,46.018 15.316,27.937 34.753,8.5 v2(47.171,8.5)
RF_nRST: R10.1 U10.19 | length 58.8
  Top Layer w0.2: 13.172,43.378 14.725,41.825 14.725,32.083 v2(25.741,21.066) ; v2(44.325,12.119) 44.325,13.05 44.7,13.425 46.591,13.425 46.911,13.105 R10.1@46.911,12.323
  Bottom Layer w0.2: U10.19@9.416,44.225 12.016,44.225 v2(13.013,43.228) ; v2(25.741,21.066) 27.236,21.066 27.8,20.502 27.8,19.794 35.309,12.286 v2(44.325,12.119)
RF_RTS: U4.AD16 U10.8 | length 92.1
  Top Layer w0.2: v2@64.575,4.939 64.729,5.093 64.729,6.146 U4.AD16@64.725,6.15
  Bottom Layer w0.2: U10.8@30.416,51.667 32.749,51.667 35.441,48.975 35.441,43.575 33.241,41.375 27.191,41.375 24.966,39.15 24.966,20.856 35.481,10.341 47.919,10.341 55.665,2.596 63.346,2.596 64.491,3.741 ; 64.525,3.741 v2(64.525,4.9)
SD_nPOWER: Q2.1 U4.P23 | length 39.8
  Top Layer w0.2: U4.P23@66.725,8.9 v2(66.75,8.9) ; Q2.1@67.375,40.45 67.6,40.225 v2(67.6,39.55) ; v2(72.125,9.7) 72.55,9.7 73.5,10.65 73.5,28.831 73.052,29.279 v2(73.052,29.898)
  Bottom Layer w0.2: v2(66.75,8.9) 67.3,9.45 71.875,9.45 v2(72.125,9.7) ; v2(67.6,39.55) 73.052,34.098 v2(73.052,29.898)
SPI_MISO: M1.20 R41.1 U4.L24 U11.9 | length 50.5
  Top Layer w0.2: U11.9@63.37,23.25 v2(68.237,23.25) ; U4.L24@67.225,9.65 67.367,9.65 67.642,9.925 71.122,9.925 72.235,11.038 72.235,17.237 70.272,19.2 v2(68.237,19.2) ; M1.20@71.275,27.9 71.324,27.949 72.274,27.949 v2(72.575,28.25) ; v2(74.989,28.256) 74.989,28.314 75.475,28.8 75.475,36.989 R41.1@77.875,39.389
  Bottom Layer w0.2: v2(68.237,19.2) v2(68.237,23.25) 68.237,27.363 69.125,28.25 v2(72.575,28.25) 74.983,28.25 v2(74.989,28.256)
SPI_MOSI: M1.21 R50.1 U4.N1 U11.8 | length 62.2
  Top Layer w0.2: v2(54.8,11.8) 54.8,16.154 56.996,18.35 v2(62.225,18.35) ; v2(55.2,8.15) 58.831,8.15 59.831,9.15 U4.N1@60.725,9.15 ; U11.8@63.37,22.725 v2(66.075,22.725) ; v2(66.075,24.35) v2(68.55,24.35) ; M1.21@71.275,26.8 71.575,27.1 72.461,27.1 v2(72.468,27.106) ; v2(75.103,27.128) 75.103,27.684 75.95,28.531 75.95,36.875 76.575,37.5 79.792,37.5 80.261,37.969 80.261,38.426 81.224,39.389 R50.1@81.3,39.389
  Bottom Layer w0.2: v2(54.8,11.8) 55.2,11.4 v2(55.2,8.15) ; v2(62.225,18.35) 62.825,18.35 66.075,21.6 v2(66.075,22.725) v2(66.075,24.35) ; v2(68.55,24.35) 68.775,26.075 69.806,27.106 v2(72.468,27.106) 75.081,27.106 v2(75.103,27.128)
SPI_nCS_GPS: M1.18 U4.R24 | length 30.5
  Top Layer w0.2: U4.R24@67.225,8.65 67.254,8.679 68.709,8.679 69.325,8.063 71.879,8.063 71.944,8.128 72.21,8.394 72.72,8.904 73.95,10.134 73.95,28.97 73.531,29.389 73.531,30.097 73.251,30.377 71.552,30.377 M1.18@71.275,30.1
SPI_nCS_SD: Micro_SD.2 R48.1 U4.T2 | length 63.9
  Top Layer w0.2: v2(60.925,19.775) v2(62.225,19.775)
  Top Layer w0.254: R48.1@72.875,40.811 72.799,40.811 72.411,41.199 72.411,41.925 72.15,42.186 72.15,46.487 73.275,47.612 Micro_SD.2@73.275,53.85 ; Micro_SD.2@73.25,53.825 Micro_SD.2@73.275,53.85 ; Micro_SD.2@73.275,53.9 Micro_SD.2@73.275,53.85 ; Micro_SD.2@73.55,54.125 Micro_SD.2@73.275,53.85
  Bottom Layer w0.2: v2(60.925,19.775) 60.274,19.775 55.654,15.155 55.654,9.371 56.625,8.4 v2(61.225,8.4) ; v2(62.225,19.775) 62.742,19.775 64.875,21.908 64.875,27.767 66.3,29.192 66.3,40.325 66.875,40.9 71.375,40.9 v2(72.4,41.925)
SPI_SCK: M1.19 Micro_SD.5 R51.2 U4.J24 U11.7 | length 66
  Top Layer w0.2: U11.7@63.37,22.225 v2(67.85,22.225) ; U4.J24@67.225,10.15 67.475,10.4 70.955,10.4 71.781,11.226 71.781,17.049 70.084,18.746 v2(67.6,18.746) ; M1.19@71.275,29 71.399,28.876 v2(72.428,28.876) ; v2(74.958,29.025) 74.958,37.114 75.792,37.948 v2(75.792,38.175) 75.792,39.082 76.099,39.389 R51.2@76.175,39.389 ; v2(76.6,42.1) Micro_SD.5@76.6,54.525
  Bottom Layer w0.2: v2(67.6,18.746) 67.85,18.996 v2(67.85,22.225) 67.85,27.751 68.975,28.876 v2(72.428,28.876) 72.442,28.876 72.585,29.02 74.953,29.02 v2(74.958,29.025) ; v2(75.792,38.175) 76.875,39.258 76.875,41.825 v2(76.6,42.1)
SWDCLK: J3.4 U4.AA24 | length 13.5
  Top Layer w0.2: U4.AA24@67.225,7.15 68.553,7.15 69.034,6.669 71.269,6.669 71.275,6.675 v2(71.5,6.675) ; v2(76.35,6.675) 77.19,6.675 78.424,5.441 78.424,5.031 J3.4@79.255,4.2
  Bottom Layer w0.2: v2(71.5,6.675) v2(76.35,6.675)
SWDIO: J3.2 U4.AC24 | length 15.1
  Top Layer w0.2: U4.AC24@67.225,6.65 67.246,6.629 68.048,6.629 68.462,6.215 v2(71.122,6.215) ; v2(75.377,6.198) 74.975,5.795 74.975,4.53 76.211,3.294 77.396,3.294 77.76,2.93 J3.2@79.255,2.93
  Bottom Layer w0.2: v2(71.122,6.215) 75.36,6.215 v2(75.377,6.198)
UART_RX_A1: J1.3 U4.AC21 U10.5 | length 85.7
  Top Layer w0.2: 53.352,3.85 54.705,3.85 56.105,5.25 J1.3@56.105,5.5 ; U4.AC21@65.975,6.65 v2(65.987,6.65) U4.AC21@66,6.65
  Bottom Layer w0.2: U10.5@30.416,44.175 28.641,44.175 24.008,39.542 24.008,20.529 35.104,9.433 47.458,9.433 55.203,1.688 65.387,1.688 66.45,2.751 66.45,6.187 v2(65.987,6.65)
  other v2: 53.193,3.7
UART_TX_A1: J1.2 U4.G1 U10.6 | length 69.7
  Top Layer w0.2: 33.125,46.75 33.25,46.75 33.737,46.263 39.096,40.904 39.096,14.229 42.675,10.65 v2(54,10.65) U4.G1@60.725,10.65 ; v2(57.35,6.675) 57.35,5.525 J1.2@57.375,5.5
  Bottom Layer w0.2: U10.6@29.863,46.322 30.141,46.6 v2(32.966,46.6) ; v2(54,10.65) 54,7.075 54.4,6.675 v2(57.35,6.675)
uC_nRST: Q3.3 U4.AC13 | length 71.2
  Top Layer w0.2: v2(51.545,46.8) 51.925,46.8 52.425,47.3 52.625,47.1 Q3.3@52.65,47.1
  Bottom Layer w0.2: v2(51.545,46.8) 49.783,46.8 49.278,47.305 43.58,47.305 42.25,45.975 42.25,15.319 46.144,11.425 48.429,11.425 56.2,3.654 62.377,3.654 63.223,4.5 63.775,4.5 64.175,4.9 64.175,5.402 63.975,5.602 v2(63.975,6.65)
VBAT: C8.2 C37.2 C47.2 C49.1 C51.1 J_BAT.2 R2.2 R11.1 R12.1 R37.2 U3.9 U3.10 U6.4 U9.4 U12.5 U15.1 U16.1 | length 111.5
  Top Layer w0.2: U3.9@63.85,36.375 U3.9@63.875,36.35
  Top Layer w0.254: v2(28.113,2.463) 28.2,2.55 R37.2@29.125,2.55 ; C51.1@47.386,41.3 C51.1@47.486,41.4 ; U15.1@49.725,57.75 U15.1@49.775,57.8
  Top Layer w0.3: C51.1@47.486,41.4 v1(48.075,41.4) ; v1(48.792,37.956) 49.644,37.956 U9.4@49.65,37.95
  Top Layer w0.4: C49.1@47.475,32 48.325,32 v1(48.35,32.025) ; C47.2@47.737,7.3 C47.2@47.828,7.209 47.725,7.105 47.725,5.9 47.65,5.825 U16.1@47.775,5.7 48.125,5.7 48.325,5.5 48.325,4.769 49.094,4 49.094,2.631 R12.1@49.4,2.325 50.9,2.325 51.4,2.825 51.4,6.213 v7(53.312,8.125) ; C8.2@61.575,35.911 v1(61.575,37) ; v1(62.75,36.318) 63.724,36.318
  Top Layer w0.5: R11.1@46.075,54.311 46.086,54.3 v1(47.175,54.3) ; R2.2@46.075,55.989 v1(46.956,55.989) ; v1(49.775,52.7) 49.775,53.225 U12.5@49.8,53.25 ; U15.1@49.775,57.8 v1(49.775,58.8) ; v1(50.2,51.125) 50.2,50.91 51.099,50.011 C37.2@51.175,50.011 51.251,50.011 52.075,49.187 52.075,48.475 v1(52.425,48.125) ; v1(51.375,58.3) 51.375,57.523 51.548,57.35 U6.4@51.55,57.35
  vcc w0.2: 60.127,37.625 60.752,37 v1(61.575,37) 62.225,36.35 v1@62.9,36.35
  Bottom Layer w0.254: v2(28.113,2.463) 28.2,2.375 v2(50.936,2.375)
  Bottom Layer w0.4: J_BAT.2@53.2,27.275 46.95,27.275 43.9,24.225 43.9,15.225 46.525,12.6 48.837,12.6 v7(53.312,8.125)
  Bottom Layer w0.5: v1(48.792,37.956) 48.075,38.673 v1(48.075,41.4) 52.425,45.75 v1(52.425,48.125) ; v1(50.2,51.125) 49.775,51.55 v1(49.775,52.7) 48.175,54.3 v1(47.175,54.3) 46.95,54.525 46.95,55.835 46.956,55.84 v1(46.956,55.989) 46.964,55.989 v1(49.775,58.8) 50.875,58.8 v1(51.375,58.3)
VCC: C2.2 C9.2 C10.2 C15.2 C16.2 M1.23 Q2.2 R10.2 R29.2 R40.2 R44.1 R47.1 U1.1 U10.4 | length 77.6
  Top Layer w0.254: v2(44.35,11.625) 44.791,11.625 R10.2@45.489,12.323 ; C2.2@56.275,54.533 C2.2@56.508,54.3 ; Q2.2@67.375,41.75 67.75,42.125 v2(67.75,42.575) ; v2(71.175,38.4) R47.1@71.175,39.389 ; v2(74.475,38.175) R40.2@74.475,39.389 ; v2(79.575,38.15) R44.1@79.575,39.389 ; R29.2@82.375,50.122 v2(82.375,51.325)
  Top Layer w0.3: C2.2@56.508,54.3 v5(57.375,54.3) ; v5(57.375,53) U1.1@58.075,53 ; v5(62.725,51.983) v5(65.475,51.983)
  Top Layer w0.4: C16.2@69.35,23.25 69.431,23.331 v1(69.431,24.606) ; C15.2@69.425,25.4 69.431,25.394 v1(69.431,24.606) ; M1.23@71.275,24.6 71.268,24.606 v1(69.431,24.606)
  vcc w0.254: v5(57.375,53) 57.575,53 57.575,54.1 v5(57.375,54.3)
  Bottom Layer w0.3: 57.575,53 61.141,53 62.158,51.983 v5(62.725,51.983) ; v5(65.475,51.983) 66.091,51.983 69.637,48.437 ; v2(67.75,42.575) 67.75,44.32 ; v2(71.175,38.4) 72.3,37.275 73.575,37.275 ; v2(79.575,38.15) 78.7,37.275 73.575,37.275 ; v2(82.375,51.325) 72.525,51.325 69.637,48.437 ; 67.75,44.32 67.75,46.55 69.637,48.437 ; 67.75,44.32 72.53,44.32 74.475,42.375 v2(74.475,38.175) 73.575,37.275
  Bottom Layer w0.5: U10.4@30.95,38.675 30.575,38.3 v1(31.435,37.44) 31.965,36.91 32.999,36.91 C9.2@33.35,36.559 33.627,36.281 35.269,36.281 C10.2@35.425,36.125
VCC_EN: R20.2 U1.4 U4.AD12 | length 83.4
  Top Layer w0.2: v2@63.475,4.242 63.475,4.552 63.212,4.815 63.212,5.324 63.725,5.837 U4.AD12@63.725,6.15
  Top Layer w0.254: U1.4@59.375,55.1 59.375,55.002 59.398,54.979 60.319,54.979 60.375,54.924 R20.2@60.375,54.8
  Bottom Layer w0.2: v2(59.725,55) 56.317,55 51.131,49.814 45.45,49.814 41.75,46.114 41.75,15.177 45.982,10.945 48.266,10.945 56.012,3.2 62.877,3.2 63.505,3.828 63.475,3.858 v2(63.475,4.154)
VCC_EXT: C1.2 C4.2 C53.1 C56.1 R21.2 U1.6 U2.7 U2.8 U5.4 U5.6 U6.2 U6.3 | length 20.6
  Top Layer w0.254: U6.2@54.2,56.475 U6.2@54.275,56.4 ; U1.6@58.075,55.1 58.078,55.103 v2(58.078,55.578) 58.078,56.364 58.075,56.367 C1.2@58.408,56.7 ; R21.2@61.275,40.411 v2(61.275,41.4) ; v5(61.662,54.25) v5@61.825,54.25 ; U5.4@62.425,55.55 62.45,55.55 62.473,55.573 v2(62.473,55.997) 62.473,56.421 C53.1@62.753,56.7 ; 62.725,49.487 U2.7@62.852,49.535
  Top Layer w0.3: v5@61.825,54.25 U5.6@62.425,54.25
  Top Layer w0.5: U6.2@54.2,56.4 54.2,56.475 U6.3@54.2,57.35 v1(54.2,58.15) ; C4.2@57.375,49.1 v1(58.175,49.1) C56.1@59.275,49.1 ; v1(58.225,58) 58.225,57.111 C1.2@58.265,57.071 ; v1(61.575,49.487) U2.8@62.25,49.487 62.725,49.487 ; 62.667,57.225 v1(62.667,58.025)
  Bottom Layer w0.254: v1(58.175,49.1) 59.975,47.3 59.975,45.6 61.275,44.3 v2(61.275,41.4)
VCC_EXT_EN: Q1.1 U4.H2 | length 65.4
  Top Layer w0.2: v2(38.6,40.65) 38.6,14.161 42.611,10.15 v2(57.934,10.15) ; v2(39.975,44.138) 40.012,44.138 42.925,47.05 Q1.1@49.2,47.05
  Bottom Layer w0.2: v2(38.6,40.65) 38.6,42.725 39.975,44.1 v2(39.975,44.138) ; v2(57.934,10.15) 57.948,10.15 58.198,10.4 v2(61.225,10.4)
VCC_LNA: C44.1 L5.1 U7.2 | length 3.6
  Top Layer w0.3: C44.1@82.375,45.689 C44.1@82.625,45.439 ; C44.1@82.625,45.495 84.232,45.495 84.3,45.564 84.327,45.536 85.257,45.536 85.387,45.667 U7.2@85.754,45.667
VCC_PA: C6.2 C11.2 C12.2 C21.2 R1.2 R53.2 U2.1 U2.2 U10.1 | length 9
  Top Layer w0.254: U2.1@62.225,46.512 U2.1@62.25,46.537 ; U2.2@62.875,46.512 U2.2@62.9,46.537 ; C21.2@64.575,42.789 C21.2@64.686,42.9
  Top Layer w0.3: v1(59.238,44.834) R53.2@60.03,44.834 ; v5(59.275,42.9) R1.2@59.95,42.9 ; C21.2@65.083,42.9 v5(65.758,42.9)
  Top Layer w0.5: C6.2@58.059,44.834 C6.2@58.075,44.834 v1(59.238,44.834) ; R53.2@60.03,44.834 R53.2@60.164,44.7 ; v1(61.625,46.544) U2.2@62.775,46.544
  Bottom Layer w0.5: U10.1@31.49,21.435 31.73,21.675 v1(32.325,21.675) 33.425,21.675 35.261,21.675 C12.2@35.425,21.839
VCC_PA_EN: R16.2 U2.5 U4.A8 | length 44.1
  Top Layer w0.2: U4.A8@62.725,12.65 62.725,15.167 63.375,15.817 v2(63.375,16.825) ; U2.5@64.2,49.487 65.31,49.487 R16.2@65.575,49.222 ; R16.2@65.65,49.212 66.45,48.412 66.45,39.728 68.239,37.939 69.102,37.939 69.908,37.133 69.908,31.062 67.621,28.775 v2(66.525,28.775)
  Top Layer w0.254: R16.2@65.475,49.311 R16.2@65.575,49.211 ; R16.2@65.5,49.275 R16.2@65.525,49.25
  Bottom Layer w0.2: v2(63.375,16.825) 63.375,18 66.525,21.15 v2(66.525,28.775)
VCC_uC: C54.2 J3.1 M1.22 Q4.2 U4.A22 U4.AD14 U4.AD23 U4.B1 U4.W1 U4.Y2 U5.1 U11.1 | length 31.7
  Top Layer w0.2: U4.AD14@64.225,6.15 64.427,5.948 v2(64.427,5.602) ; J3.1@80.525,2.93 80.635,2.82 81.346,2.82 v2(81.356,2.81)
  Top Layer w0.254: v2(45.2,33.025) 45.202,33.027 45.202,33.577 45.375,33.75 Q4.2@45.825,33.75 ; U11.1@60.83,23.725 60.861,23.756 v2(60.861,25.15)
  Top Layer w0.3: v5(59.65,7.65) U4.W1@60.725,7.65 60.975,7.4 U4.Y2@61.225,7.4 U4.Y2@61.2,7.4 ; U4.B1@60.725,12.15 v5(60.725,13.226) ; U5.1@64.592,54.25 v5(65.475,54.25) ; U4.A22@66.225,12.65 v5(66.225,13.475) ; U4.AD23@66.725,6.15 v5(67.85,6.15)
  Top Layer w0.4: C54.2@64.097,53 v5(65.475,53) ; C54.2@64.175,53.1 C54.2@64.175,53.154 ; M1.22@71.275,25.7 71.375,25.6 v1(72.775,25.6)
  Bottom Layer w0.254: v2(45.2,33.025) 46.875,31.35 52.45,31.35 57.95,25.85 60.161,25.85 v2(60.861,25.15)
VCC_USB: C55.2 J_charge_5v.2 Q5.6 U9.9 | length 23.1
  Top Layer w0.4: v1(49.275,40.008) 49.275,40.567 C55.2@49.708,41 ; U9.9@49.85,35.39 v1(49.85,34.275) 50.125,34 Q5.6@50.125,33 ; J_charge_5v.2@57.7,27.82 59.095,27.82 v1(59.15,27.875)
  Bottom Layer w0.4: v1(49.275,40.008) 49.85,39.433 v1(49.85,34.275) 52.75,34.275 v1(59.15,27.875)
VCC_USB_ON: C5.2 LED1.1 LED2.1 LED3.1 Q5.4 U3.1 U3.2 | length 70.3
  Top Layer w0.254: LED3.1@32.625,2.55 32.625,1.125 ; LED2.1@34.275,2.55 34.275,1.125 ; LED1.1@35.875,2.55 35.875,1.125 34.275,1.125 ; v2(36.175,33.45) 36.175,29.625 35.275,28.725 35.275,15.05 27.025,6.8 27.025,2.125 28.025,1.125 32.625,1.125 ; v2(40.5,33.45) 42.225,33.45 v2(43.375,34.6) ; Q5.4@52.025,33 52.775,33 v2(52.875,33.1) ; v5@62.951,33.1 v5(62.829,33.1) 62.857,33.128 63.352,33.128 U3.1@63.375,33.151 ; C5.2@63.48,31.971 63.375,32.076 U3.1@63.375,33.151 ; U3.2@63.875,33.25 U3.1@63.375,33.25 U3.1@63.375,33.151 ; 32.625,1.125 34.275,1.125
  Bottom Layer w0.254: v2(36.175,33.45) v2(40.5,33.45) ; v2(43.375,34.6) 43.925,35.15 47.01,35.15 49.06,33.1 v2(52.875,33.1)
pads on no net: J3.0 J3.3 J3.6 M1.5 M1.6 M1.14 M1.17 Micro_SD.9 U4.A10 U4.A14 U4.A16 U4.AB2 U4.AC5 U4.AC9 U4.AD4 U4.AD6 U4.AD10 U4.AD22 U4.B3 U4.B15 U4.B19 U4.M2 U4.P2 U4.R1 U10.9 U10.10 U10.11 U10.12 U10.13 U12.1 U13.2 U13.3 U13.4 X1.4
copper on no net: | length 0.1
  Top Layer w0.2: v2@64.475,12.15 v2(64.475,12.175) ; v2@65.475,12.15 v2(65.475,12.175)
  other v1: 83.661,49.502
  other v2: 61.225,8.9 61.225,9.4

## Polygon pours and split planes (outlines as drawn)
VCC_uC on vcc "vcc-VCC_uC" (solid, remove dead copper, pour order 31): 64.45,59.975 64.475,59.95 64.475,48.2 65.975,48.2 65.861,48.086 65.861,31.05 71.775,31.05 71.775,23.05 66.525,23.05 66.525,26.1 58.989,26.1 58.975,26.086 58.975,13.875 55.9,13.875 55.9,0.013 55.912,0 99.975,0 99.975,59.993
VCC_EXT on vcc "vcc-VCC_EXT" (solid, pour order 29): 54.225,59.95 54.225,54.95 54.25,54.925 54.325,55 58.948,55 58.948,50.498 58.946,50.5 55.775,50.5 55.775,48.175 55.8,48.2 63.975,48.2 63.975,59.975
